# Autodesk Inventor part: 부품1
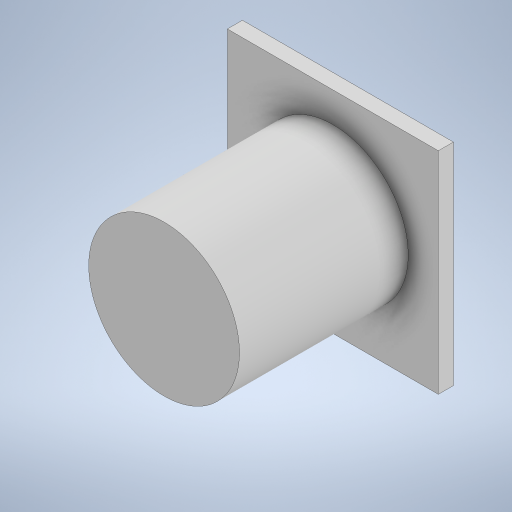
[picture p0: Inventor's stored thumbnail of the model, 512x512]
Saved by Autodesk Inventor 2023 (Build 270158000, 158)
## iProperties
Created: 2025-05
Part Number: 부품1
Material: 일반
Document SubType Name: Modeling
Designer: user
Density: 1 g/cm^3
Appearance: 기본값
Author: user
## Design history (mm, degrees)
sketch "스케치3"
  geometry: C1 r 50 at (0, 0); 1 further point
  constraints: 1 centre point, 1 coincident
  dimensions: "d0" = 100 diameter of C1
extrude "돌출1" new body sketch "스케치3" distance "d1" = 122; taper "d2" = 0 deg
feature "쉘1" dims "d11" = 5
sketch "스케치9"
  geometry: L1 (-70, -70)-(70, -70); L2 (70, -70)-(70, 70); L3 (70, 70)-(-70, 70); L4 (-70, 70)-(-70, -70); L5 (-70, -70)-(70, 70); L6 (70, -70)-(-70, 70); 1 further point
  constraints: 12 end point, 2 midpoint, 2 parallel, 1 horizontal, 1 perpendicular
  dimensions: "d12" = 140 distance of L3.end L2.end; "d13" = 140 distance of L2.end L1.end
extrude "돌출4" join sketch "스케치9" distance "d14" = 10; taper "d15" = 0 deg
node "솔리드1"
